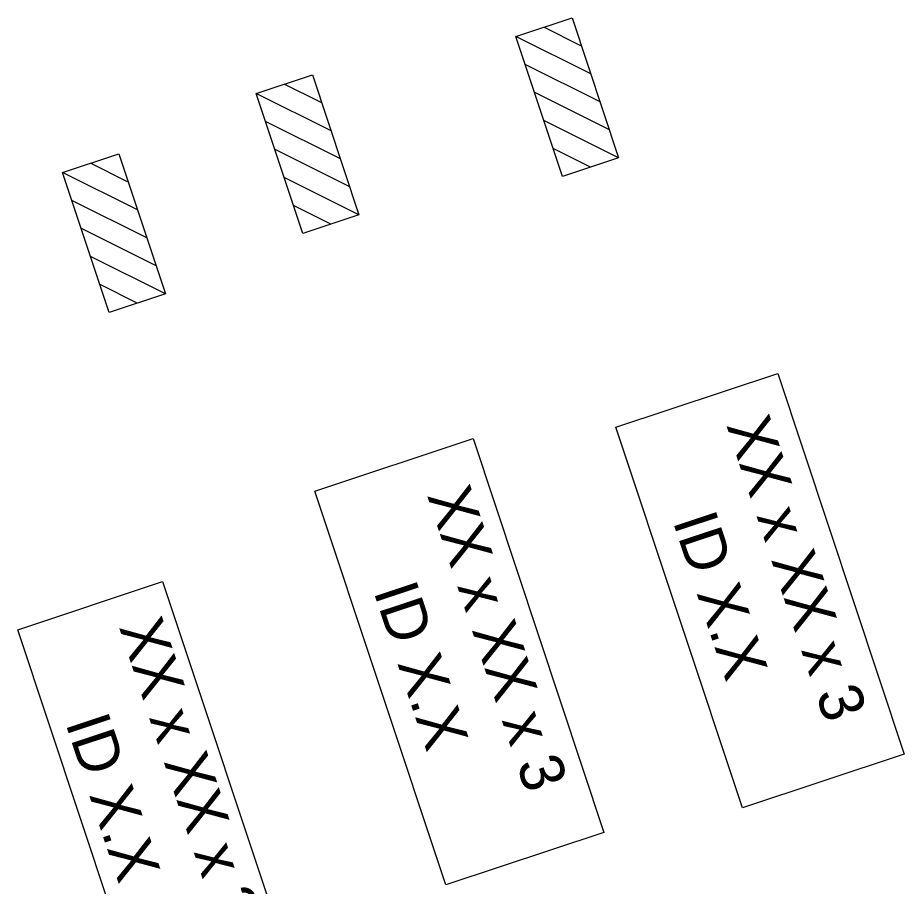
# Model space of a CAD drawing. Extents: x 400935 to 481562, y 415700 to 505362.
# Drawn here: x 402282.6 to 402462.8, y 418405.8 to 418582.3 of the extents above; entities that cross this region are included whole.
import ezdxf

# ---------------------------------------------------------------- set-up
doc = ezdxf.new("R2010")
doc.units = 0
for name, color, linetype in [('Silt Basin Type B Both CELL', 7, 'Continuous'), ('Silt Basin Type B CG CELL', 7, 'Continuous'), ('Silt Basin Type B Final CELL', 7, 'Continuous'), ('Silt Basin Type B Note Both CELL', 7, 'Continuous'), ('Silt Basin Type B Note CG CELL', 7, 'Continuous'), ('Silt Basin Type B Note Final CELL', 7, 'Continuous')]:
    doc.layers.add(name, color=color, linetype=linetype)

msp = doc.modelspace()

# ---------------------------------------------------------------- linework, layer by layer
at = {"layer": 'Silt Basin Type B Both CELL'}
for p, q in [((402344.32, 418565.08), (402336.8, 418568.85)), ((402344.32, 418565.08), (402336.8, 418568.85)), ((402344.32, 418565.08), (402336.8, 418568.85)), ((402344.32, 418565.08), (402336.8, 418568.85)), ((402344.32, 418565.08), (402336.8, 418568.85)), ((402344.32, 418565.08), (402336.8, 418568.85)), ((402346.32, 418559.37), (402331.1, 418566.96)), ((402346.32, 418559.37), (402331.1, 418566.96)), ((402346.32, 418559.37), (402331.1, 418566.96)), ((402346.32, 418559.37), (402331.1, 418566.96)), ((402346.32, 418559.37), (402331.1, 418566.96)), ((402346.32, 418559.37), (402331.1, 418566.96)), ((402348.22, 418553.67), (402333, 418561.26)), ((402348.22, 418553.67), (402333, 418561.26)), ((402348.22, 418553.67), (402333, 418561.26)), ((402348.22, 418553.67), (402333, 418561.26)), ((402348.22, 418553.67), (402333, 418561.26)), ((402348.22, 418553.67), (402333, 418561.26)), ((402350.11, 418547.98), (402334.94, 418555.58)), ((402350.11, 418547.98), (402334.94, 418555.58)), ((402350.11, 418547.98), (402334.94, 418555.58)), ((402350.11, 418547.98), (402334.94, 418555.58)), ((402350.11, 418547.98), (402334.94, 418555.58)), ((402350.11, 418547.98), (402334.94, 418555.58)), ((402352, 418542.29), (402336.78, 418549.87)), ((402352, 418542.29), (402336.78, 418549.87)), ((402352, 418542.29), (402336.78, 418549.87)), ((402352, 418542.29), (402336.78, 418549.87)), ((402352, 418542.29), (402336.78, 418549.87)), ((402352, 418542.29), (402336.78, 418549.87)), ((402346.26, 418540.38), (402338.72, 418544.2)), ((402346.26, 418540.38), (402338.72, 418544.2)), ((402346.26, 418540.38), (402338.72, 418544.2)), ((402346.26, 418540.38), (402338.72, 418544.2)), ((402346.26, 418540.38), (402338.72, 418544.2)), ((402346.26, 418540.38), (402338.72, 418544.2))]:
    msp.add_line(p, q, dxfattribs=at)
msp.add_lwpolyline([(402342.54, 418570.76), (402352, 418542.29), (402340.57, 418538.49), (402331.1, 418566.96)], close=True, dxfattribs=at)
msp.add_lwpolyline([(402342.54, 418570.76), (402352, 418542.29), (402340.57, 418538.49), (402331.1, 418566.96)], close=True, dxfattribs=at)
msp.add_lwpolyline([(402342.54, 418570.76), (402352, 418542.29), (402340.57, 418538.49), (402331.1, 418566.96)], close=True, dxfattribs=at)
msp.add_lwpolyline([(402342.54, 418570.76), (402352, 418542.29), (402340.57, 418538.49), (402331.1, 418566.96)], close=True, dxfattribs=at)
msp.add_lwpolyline([(402342.54, 418570.76), (402352, 418542.29), (402340.57, 418538.49), (402331.1, 418566.96)], close=True, dxfattribs=at)
msp.add_lwpolyline([(402342.54, 418570.76), (402352, 418542.29), (402340.57, 418538.49), (402331.1, 418566.96)], close=True, dxfattribs=at)
at = {"layer": 'Silt Basin Type B CG CELL'}
for p, q in [((402397.1, 418576.66), (402389.57, 418580.43)), ((402397.1, 418576.66), (402389.57, 418580.43)), ((402397.1, 418576.66), (402389.57, 418580.43)), ((402397.1, 418576.66), (402389.57, 418580.43)), ((402397.1, 418576.66), (402389.57, 418580.43)), ((402397.1, 418576.66), (402389.57, 418580.43)), ((402399.1, 418570.95), (402383.88, 418578.54)), ((402399.1, 418570.95), (402383.88, 418578.54)), ((402399.1, 418570.95), (402383.88, 418578.54)), ((402399.1, 418570.95), (402383.88, 418578.54)), ((402399.1, 418570.95), (402383.88, 418578.54)), ((402399.1, 418570.95), (402383.88, 418578.54)), ((402400.99, 418565.26), (402385.77, 418572.84)), ((402400.99, 418565.26), (402385.77, 418572.84)), ((402400.99, 418565.26), (402385.77, 418572.84)), ((402400.99, 418565.26), (402385.77, 418572.84)), ((402400.99, 418565.26), (402385.77, 418572.84)), ((402400.99, 418565.26), (402385.77, 418572.84)), ((402402.89, 418559.56), (402387.71, 418567.17)), ((402402.89, 418559.56), (402387.71, 418567.17)), ((402402.89, 418559.56), (402387.71, 418567.17)), ((402402.89, 418559.56), (402387.71, 418567.17)), ((402402.89, 418559.56), (402387.71, 418567.17)), ((402402.89, 418559.56), (402387.71, 418567.17)), ((402404.78, 418553.87), (402389.56, 418561.46)), ((402404.78, 418553.87), (402389.56, 418561.46)), ((402404.78, 418553.87), (402389.56, 418561.46)), ((402404.78, 418553.87), (402389.56, 418561.46)), ((402404.78, 418553.87), (402389.56, 418561.46)), ((402404.78, 418553.87), (402389.56, 418561.46)), ((402399.04, 418551.96), (402391.5, 418555.78)), ((402399.04, 418551.96), (402391.5, 418555.78)), ((402399.04, 418551.96), (402391.5, 418555.78)), ((402399.04, 418551.96), (402391.5, 418555.78)), ((402399.04, 418551.96), (402391.5, 418555.78)), ((402399.04, 418551.96), (402391.5, 418555.78))]:
    msp.add_line(p, q, dxfattribs=at)
msp.add_lwpolyline([(402395.32, 418582.34), (402404.78, 418553.87), (402393.34, 418550.07), (402383.88, 418578.54)], close=True, dxfattribs=at)
msp.add_lwpolyline([(402395.32, 418582.34), (402404.78, 418553.87), (402393.34, 418550.07), (402383.88, 418578.54)], close=True, dxfattribs=at)
msp.add_lwpolyline([(402395.32, 418582.34), (402404.78, 418553.87), (402393.34, 418550.07), (402383.88, 418578.54)], close=True, dxfattribs=at)
msp.add_lwpolyline([(402395.32, 418582.34), (402404.78, 418553.87), (402393.34, 418550.07), (402383.88, 418578.54)], close=True, dxfattribs=at)
msp.add_lwpolyline([(402395.32, 418582.34), (402404.78, 418553.87), (402393.34, 418550.07), (402383.88, 418578.54)], close=True, dxfattribs=at)
msp.add_lwpolyline([(402395.32, 418582.34), (402404.78, 418553.87), (402393.34, 418550.07), (402383.88, 418578.54)], close=True, dxfattribs=at)
at = {"layer": 'Silt Basin Type B Final CELL'}
for p, q in [((402304.95, 418549.01), (402297.43, 418552.78)), ((402304.95, 418549.01), (402297.43, 418552.78)), ((402304.95, 418549.01), (402297.43, 418552.78)), ((402304.95, 418549.01), (402297.43, 418552.78)), ((402304.95, 418549.01), (402297.43, 418552.78)), ((402304.95, 418549.01), (402297.43, 418552.78)), ((402306.96, 418543.3), (402291.74, 418550.89)), ((402306.96, 418543.3), (402291.74, 418550.89)), ((402306.96, 418543.3), (402291.74, 418550.89)), ((402306.96, 418543.3), (402291.74, 418550.89)), ((402306.96, 418543.3), (402291.74, 418550.89)), ((402306.96, 418543.3), (402291.74, 418550.89)), ((402308.85, 418537.61), (402293.63, 418545.2)), ((402308.85, 418537.61), (402293.63, 418545.2)), ((402308.85, 418537.61), (402293.63, 418545.2)), ((402308.85, 418537.61), (402293.63, 418545.2)), ((402308.85, 418537.61), (402293.63, 418545.2)), ((402308.85, 418537.61), (402293.63, 418545.2)), ((402310.74, 418531.92), (402295.57, 418539.52)), ((402310.74, 418531.92), (402295.57, 418539.52)), ((402310.74, 418531.92), (402295.57, 418539.52)), ((402310.74, 418531.92), (402295.57, 418539.52)), ((402310.74, 418531.92), (402295.57, 418539.52)), ((402310.74, 418531.92), (402295.57, 418539.52)), ((402312.64, 418526.22), (402297.42, 418533.81)), ((402312.64, 418526.22), (402297.42, 418533.81)), ((402312.64, 418526.22), (402297.42, 418533.81)), ((402312.64, 418526.22), (402297.42, 418533.81)), ((402312.64, 418526.22), (402297.42, 418533.81)), ((402312.64, 418526.22), (402297.42, 418533.81)), ((402306.89, 418524.31), (402299.36, 418528.13)), ((402306.89, 418524.31), (402299.36, 418528.13)), ((402306.89, 418524.31), (402299.36, 418528.13)), ((402306.89, 418524.31), (402299.36, 418528.13)), ((402306.89, 418524.31), (402299.36, 418528.13)), ((402306.89, 418524.31), (402299.36, 418528.13))]:
    msp.add_line(p, q, dxfattribs=at)
msp.add_lwpolyline([(402303.17, 418554.69), (402312.64, 418526.22), (402301.2, 418522.42), (402291.74, 418550.89)], close=True, dxfattribs=at)
msp.add_lwpolyline([(402303.17, 418554.69), (402312.64, 418526.22), (402301.2, 418522.42), (402291.74, 418550.89)], close=True, dxfattribs=at)
msp.add_lwpolyline([(402303.17, 418554.69), (402312.64, 418526.22), (402301.2, 418522.42), (402291.74, 418550.89)], close=True, dxfattribs=at)
msp.add_lwpolyline([(402303.17, 418554.69), (402312.64, 418526.22), (402301.2, 418522.42), (402291.74, 418550.89)], close=True, dxfattribs=at)
msp.add_lwpolyline([(402303.17, 418554.69), (402312.64, 418526.22), (402301.2, 418522.42), (402291.74, 418550.89)], close=True, dxfattribs=at)
msp.add_lwpolyline([(402303.17, 418554.69), (402312.64, 418526.22), (402301.2, 418522.42), (402291.74, 418550.89)], close=True, dxfattribs=at)
at = {"layer": 'Silt Basin Type B Note Both CELL'}
msp.add_lwpolyline([(402375.18, 418496.79), (402401.78, 418416.76), (402369.66, 418406.09), (402343.05, 418486.12)], close=True, dxfattribs=at)
msp.add_lwpolyline([(402375.18, 418496.79), (402401.78, 418416.76), (402369.66, 418406.09), (402343.05, 418486.12)], close=True, dxfattribs=at)
msp.add_lwpolyline([(402375.18, 418496.79), (402401.78, 418416.76), (402369.66, 418406.09), (402343.05, 418486.12)], close=True, dxfattribs=at)
msp.add_lwpolyline([(402375.18, 418496.79), (402401.78, 418416.76), (402369.66, 418406.09), (402343.05, 418486.12)], close=True, dxfattribs=at)
msp.add_lwpolyline([(402375.18, 418496.79), (402401.78, 418416.76), (402369.66, 418406.09), (402343.05, 418486.12)], close=True, dxfattribs=at)
msp.add_lwpolyline([(402375.18, 418496.79), (402401.78, 418416.76), (402369.66, 418406.09), (402343.05, 418486.12)], close=True, dxfattribs=at)
at = {"layer": 'Silt Basin Type B Note CG CELL'}
msp.add_lwpolyline([(402437.12, 418510.05), (402462.84, 418432.68), (402429.96, 418421.76), (402404.24, 418499.12)], close=True, dxfattribs=at)
msp.add_lwpolyline([(402437.12, 418510.05), (402462.84, 418432.68), (402429.96, 418421.76), (402404.24, 418499.12)], close=True, dxfattribs=at)
msp.add_lwpolyline([(402437.12, 418510.05), (402462.84, 418432.68), (402429.96, 418421.76), (402404.24, 418499.12)], close=True, dxfattribs=at)
msp.add_lwpolyline([(402437.12, 418510.05), (402462.84, 418432.68), (402429.96, 418421.76), (402404.24, 418499.12)], close=True, dxfattribs=at)
msp.add_lwpolyline([(402437.12, 418510.05), (402462.84, 418432.68), (402429.96, 418421.76), (402404.24, 418499.12)], close=True, dxfattribs=at)
msp.add_lwpolyline([(402437.12, 418510.05), (402462.84, 418432.68), (402429.96, 418421.76), (402404.24, 418499.12)], close=True, dxfattribs=at)
at = {"layer": 'Silt Basin Type B Note Final CELL'}
msp.add_lwpolyline([(402312.08, 418467.75), (402337.38, 418391.64), (402307.93, 418381.86), (402282.63, 418457.96)], close=True, dxfattribs=at)
msp.add_lwpolyline([(402312.08, 418467.75), (402337.38, 418391.64), (402307.93, 418381.86), (402282.63, 418457.96)], close=True, dxfattribs=at)
msp.add_lwpolyline([(402312.08, 418467.75), (402337.38, 418391.64), (402307.93, 418381.86), (402282.63, 418457.96)], close=True, dxfattribs=at)
msp.add_lwpolyline([(402312.08, 418467.75), (402337.38, 418391.64), (402307.93, 418381.86), (402282.63, 418457.96)], close=True, dxfattribs=at)
msp.add_lwpolyline([(402312.08, 418467.75), (402337.38, 418391.64), (402307.93, 418381.86), (402282.63, 418457.96)], close=True, dxfattribs=at)
msp.add_lwpolyline([(402312.08, 418467.75), (402337.38, 418391.64), (402307.93, 418381.86), (402282.63, 418457.96)], close=True, dxfattribs=at)

# ---------------------------------------------------------------- texts
at = {"layer": 'Silt Basin Type B Note Both CELL'}
for s, p in [('XX x XX x 3', (402365.8, 418485.3)), ('XX x XX x 3', (402365.8, 418485.3)), ('XX x XX x 3', (402365.8, 418485.3)), ('XX x XX x 3', (402365.8, 418485.3)), ('XX x XX x 3', (402365.8, 418485.3)), ('XX x XX x 3', (402365.8, 418485.3)), ('ID X.X', (402354.89, 418465.82)), ('ID X.X', (402354.89, 418465.82)), ('ID X.X', (402354.89, 418465.82)), ('ID X.X', (402354.89, 418465.82)), ('ID X.X', (402354.89, 418465.82)), ('ID X.X', (402354.89, 418465.82))]:
    msp.add_text(s, height=9, rotation=288.3867, dxfattribs=at).set_placement(p)
at = {"layer": 'Silt Basin Type B Note CG CELL'}
for s, p in [('XX x XX x 3', (402426.63, 418499.56)), ('XX x XX x 3', (402426.63, 418499.56)), ('XX x XX x 3', (402426.63, 418499.56)), ('XX x XX x 3', (402426.63, 418499.56)), ('XX x XX x 3', (402426.63, 418499.56)), ('XX x XX x 3', (402426.63, 418499.56)), ('ID X.X', (402415.72, 418480.07)), ('ID X.X', (402415.72, 418480.07)), ('ID X.X', (402415.72, 418480.07)), ('ID X.X', (402415.72, 418480.07)), ('ID X.X', (402415.72, 418480.07)), ('ID X.X', (402415.72, 418480.07))]:
    msp.add_text(s, height=9, rotation=288.3867, dxfattribs=at).set_placement(p)
at = {"layer": 'Silt Basin Type B Note Final CELL'}
for s, p in [('XX x XX x 3', (402303.18, 418458.52)), ('XX x XX x 3', (402303.18, 418458.52)), ('XX x XX x 3', (402303.18, 418458.52)), ('XX x XX x 3', (402303.18, 418458.52)), ('XX x XX x 3', (402303.18, 418458.52)), ('XX x XX x 3', (402303.18, 418458.52)), ('ID X.X', (402292.26, 418439.04)), ('ID X.X', (402292.26, 418439.04)), ('ID X.X', (402292.26, 418439.04)), ('ID X.X', (402292.26, 418439.04)), ('ID X.X', (402292.26, 418439.04)), ('ID X.X', (402292.26, 418439.04))]:
    msp.add_text(s, height=9, rotation=288.3867, dxfattribs=at).set_placement(p)

doc.saveas('drawing.dxf')
